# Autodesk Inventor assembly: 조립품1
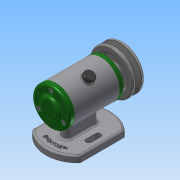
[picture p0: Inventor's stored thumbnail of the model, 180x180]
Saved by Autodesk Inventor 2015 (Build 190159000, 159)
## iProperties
Created: 2022-02
Part Number: 조립품1
Document SubType Name: Assembly
Designer: 학생용
Author: 학생용
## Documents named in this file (14)
- C:\Users\학생용\Desktop\720206V1030\조립품1.iam
- C:\Users\학생용\Desktop\720206V1030\본체.ipt
- C:\Users\학생용\Desktop\720206V1030\축.ipt
- C:\Users\학생용\Desktop\720206V1030\키 3 x 3 x 12.ipt
- C:\Users\학생용\Desktop\720206V1030\베어링 6002.ipt
- C:\Users\학생용\Desktop\720206V1030\앞커버.ipt
- C:\Users\학생용\Desktop\720206V1030\볼트 M4 x 10.ipt
- C:\Users\학생용\Desktop\720206V1030\오일 실 15 x 25 x 7.ipt
- C:\Users\학생용\Desktop\720206V1030\뒤커버.ipt
- C:\Users\학생용\Desktop\720206V1030\V벨트풀리.ipt
- C:\Users\학생용\Desktop\720206V1030\평와셔 8 x 17.ipt
- C:\Users\학생용\Desktop\720206V1030\스프링와셔 8.ipt
- C:\Users\학생용\Desktop\720206V1030\너트 M8.ipt
- C:\Users\학생용\Desktop\720206V1030\고무 캡.ipt
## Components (2 placed, 2 different names)
1. V벨트풀리:1
2. 고무 캡:1
